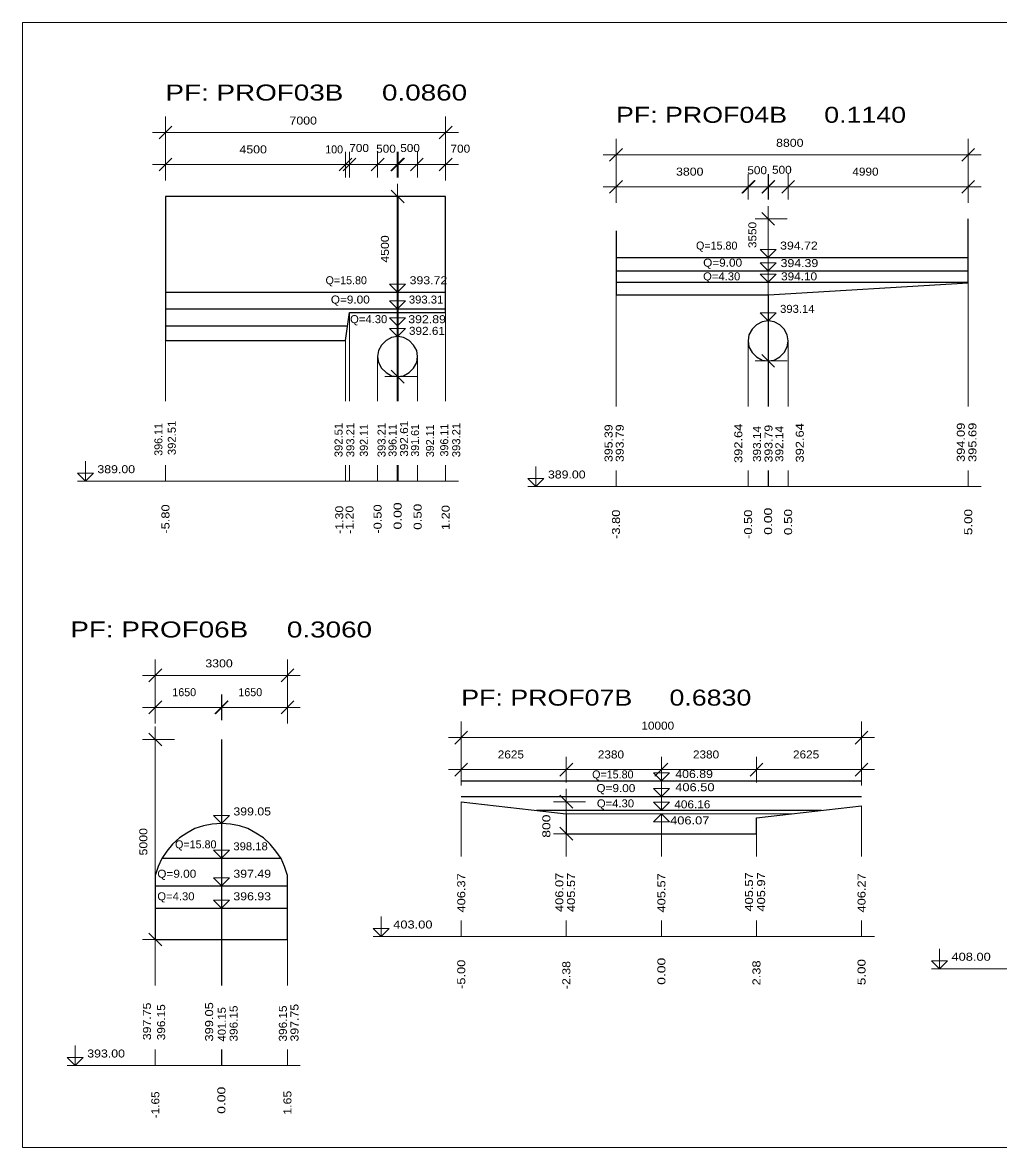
# Model space of a CAD drawing. Extents: x 7 to 442, y -393 to 441.
# Drawn here: x 17.84 to 42.23, y 76.44 to 104.55 of the extents above; entities that cross this region are included whole.
import ezdxf

# ---------------------------------------------------------------- set-up
doc = ezdxf.new("R2010")
doc.units = 0
doc.header["$LTSCALE"] = 0.08
doc.layers.add('63', color=7, linetype='Continuous', lineweight=13)
doc.layers.add('7', color=7, linetype='Continuous', lineweight=13)

msp = doc.modelspace()

# ---------------------------------------------------------------- linework, layer by layer
at = {"layer": '63'}
msp.add_lwpolyline([(17.844, 76.435), (17.844, 104.551), (38.081, 104.551), (58.318, 104.551), (58.318, 76.435), (38.081, 76.435)], close=True, dxfattribs=at)
at = {"layer": '7'}
for p, q in [((21.415, 100.6), (21.415, 102.2)), ((28.415, 100.6), (28.415, 102.2)), ((21.095, 101.8), (28.735, 101.8)), ((21.255, 101.64), (21.575, 101.96)), ((28.255, 101.64), (28.575, 101.96)), ((32.671, 100.044), (32.671, 101.644)), ((41.471, 100.044), (41.471, 101.644)), ((21.415, 100.68), (21.415, 101.32)), ((21.415, 100.68), (21.415, 101.32)), ((25.915, 100.68), (25.915, 101.32)), ((26.015, 100.68), (26.015, 101.32)), ((26.715, 100.68), (26.715, 101.32)), ((27.205, 100.68), (27.205, 101.32)), ((27.215, 100.68), (27.215, 101.32)), ((27.215, 100.68), (27.215, 101.32)), ((27.215, 100.68), (27.215, 101.32)), ((27.225, 100.68), (27.225, 101.32)), ((27.225, 100.68), (27.225, 101.32)), ((27.225, 100.68), (27.225, 101.32)), ((27.715, 100.68), (27.715, 101.32)), ((28.415, 100.68), (28.415, 101.32)), ((28.415, 100.68), (28.415, 101.32)), ((32.351, 101.244), (41.791, 101.244)), ((32.511, 101.084), (32.831, 101.404)), ((41.311, 101.084), (41.631, 101.404)), ((21.095, 101), (28.735, 101)), ((21.255, 100.84), (21.575, 101.16)), ((21.255, 100.84), (21.575, 101.16)), ((25.755, 100.84), (26.075, 101.16)), ((25.855, 100.84), (26.175, 101.16)), ((26.555, 100.84), (26.875, 101.16)), ((27.045, 100.84), (27.365, 101.16)), ((27.055, 100.84), (27.375, 101.16)), ((27.055, 100.84), (27.375, 101.16)), ((27.055, 100.84), (27.375, 101.16)), ((27.065, 100.84), (27.385, 101.16)), ((27.065, 100.84), (27.385, 101.16)), ((27.065, 100.84), (27.385, 101.16)), ((27.535, 100.84), (27.855, 101.16)), ((27.535, 100.84), (27.855, 101.16)), ((28.255, 100.84), (28.575, 101.16)), ((28.255, 100.84), (28.575, 101.16)), ((32.671, 100.124), (32.671, 100.764)), ((32.671, 100.124), (32.671, 100.764)), ((35.971, 100.124), (35.971, 100.764)), ((36.471, 100.124), (36.471, 100.764)), ((36.471, 100.124), (36.471, 100.764)), ((36.471, 100.124), (36.471, 100.764)), ((36.481, 100.124), (36.481, 100.764)), ((36.481, 100.124), (36.481, 100.764)), ((36.971, 100.124), (36.971, 100.764)), ((41.471, 100.124), (41.471, 100.764)), ((41.471, 100.124), (41.471, 100.764)), ((27.215, 95.54), (27.215, 100.52)), ((32.351, 100.444), (41.791, 100.444)), ((32.511, 100.284), (32.831, 100.604)), ((32.511, 100.284), (32.831, 100.604)), ((35.811, 100.284), (36.131, 100.604)), ((35.831, 100.284), (36.151, 100.604)), ((35.831, 100.284), (36.151, 100.604)), ((36.311, 100.284), (36.631, 100.604)), ((36.311, 100.284), (36.631, 100.604)), ((36.311, 100.284), (36.631, 100.604)), ((36.321, 100.284), (36.641, 100.604)), ((36.321, 100.284), (36.641, 100.604)), ((36.811, 100.284), (37.131, 100.604)), ((41.311, 100.284), (41.631, 100.604)), ((41.311, 100.284), (41.631, 100.604)), ((21.415, 95.087), (21.415, 100.2)), ((26.895, 100.2), (27.695, 100.2)), ((27.375, 100.04), (27.055, 100.36)), ((27.205, 95.087), (27.205, 100.2)), ((27.225, 95.087), (27.225, 100.2)), ((28.415, 95.087), (28.415, 100.2)), ((36.471, 95.934), (36.471, 99.964)), ((36.151, 99.644), (36.951, 99.644)), ((36.631, 99.484), (36.311, 99.804)), ((41.471, 94.955), (41.471, 99.644)), ((32.671, 94.955), (32.671, 99.344)), ((41.471, 94.955), (41.471, 98.044)), ((32.671, 94.955), (32.671, 97.744)), ((36.471, 94.955), (36.471, 97.744)), ((36.481, 94.955), (36.481, 97.744)), ((26.015, 95.087), (26.015, 97.3)), ((27.215, 95.087), (27.215, 97.3)), ((27.225, 95.087), (27.225, 97.3)), ((28.415, 95.087), (28.415, 97.3)), ((36.471, 94.955), (36.471, 97.094)), ((36.471, 97.094), (36.481, 97.094)), ((36.481, 94.955), (36.481, 97.094)), ((21.415, 95.087), (21.415, 96.6)), ((25.915, 95.087), (25.915, 96.6)), ((27.215, 95.087), (27.215, 96.7)), ((27.225, 95.087), (27.225, 96.7)), ((35.971, 94.955), (35.971, 96.594)), ((36.971, 94.955), (36.971, 96.594)), ((26.715, 95.087), (26.715, 96.2)), ((27.715, 95.087), (27.715, 96.2)), ((36.631, 95.934), (36.311, 96.254)), ((36.151, 96.094), (36.951, 96.094)), ((36.471, 94.955), (36.471, 96.094)), ((26.895, 95.7), (27.695, 95.7)), ((27.375, 95.54), (27.055, 95.86)), ((27.215, 95.087), (27.215, 95.7)), ((21.415, 93.087), (21.415, 93.487)), ((21.415, 93.087), (21.415, 93.487)), ((25.915, 93.087), (25.915, 93.487)), ((26.015, 93.087), (26.015, 93.487)), ((26.715, 93.087), (26.715, 93.487)), ((27.205, 93.087), (27.205, 93.487)), ((27.215, 93.087), (27.215, 93.487)), ((27.215, 93.087), (27.215, 93.487)), ((27.215, 93.087), (27.215, 93.487)), ((27.225, 93.087), (27.225, 93.487)), ((27.225, 93.087), (27.225, 93.487)), ((27.225, 93.087), (27.225, 93.487)), ((27.715, 93.087), (27.715, 93.487)), ((28.415, 93.087), (28.415, 93.487)), ((28.415, 93.087), (28.415, 93.487)), ((32.671, 92.955), (32.671, 93.355)), ((32.671, 92.955), (32.671, 93.355)), ((35.971, 92.955), (35.971, 93.355)), ((36.471, 92.955), (36.471, 93.355)), ((36.471, 92.955), (36.471, 93.355)), ((36.471, 92.955), (36.471, 93.355)), ((36.481, 92.955), (36.481, 93.355)), ((36.481, 92.955), (36.481, 93.355)), ((36.971, 92.955), (36.971, 93.355)), ((41.471, 92.955), (41.471, 93.355)), ((41.471, 92.955), (41.471, 93.355)), ((19.215, 93.087), (28.735, 93.087)), ((30.471, 92.955), (41.791, 92.955)), ((21.162, 87.034), (21.162, 88.634)), ((24.462, 87.034), (24.462, 88.634)), ((21.002, 88.074), (21.322, 88.394)), ((24.302, 88.074), (24.622, 88.394)), ((20.842, 88.234), (24.782, 88.234)), ((21.162, 87.114), (21.162, 87.754)), ((21.162, 87.114), (21.162, 87.754)), ((22.812, 87.114), (22.812, 87.754)), ((22.812, 87.114), (22.812, 87.754)), ((22.812, 87.114), (22.812, 87.754)), ((22.822, 87.114), (22.822, 87.754)), ((22.822, 87.114), (22.822, 87.754)), ((24.462, 87.114), (24.462, 87.754)), ((24.462, 87.114), (24.462, 87.754)), ((21.002, 87.274), (21.322, 87.594)), ((21.002, 87.274), (21.322, 87.594)), ((22.652, 87.274), (22.972, 87.594)), ((22.652, 87.274), (22.972, 87.594)), ((22.652, 87.274), (22.972, 87.594)), ((22.662, 87.274), (22.982, 87.594)), ((22.662, 87.274), (22.982, 87.594)), ((24.302, 87.274), (24.622, 87.594)), ((24.302, 87.274), (24.622, 87.594)), ((20.842, 87.434), (24.782, 87.434)), ((21.162, 81.474), (21.162, 86.954)), ((28.805, 85.478), (28.805, 87.078)), ((38.805, 85.478), (38.805, 87.078)), ((20.842, 86.634), (21.642, 86.634)), ((21.322, 86.474), (21.002, 86.794)), ((22.812, 80.484), (22.812, 86.634)), ((22.822, 80.484), (22.822, 86.634)), ((28.485, 86.678), (39.125, 86.678)), ((28.645, 86.518), (28.965, 86.838)), ((38.645, 86.518), (38.965, 86.838)), ((28.645, 85.718), (28.965, 86.038)), ((28.805, 85.558), (28.805, 86.198)), ((31.27, 85.718), (31.59, 86.038)), ((31.27, 85.718), (31.59, 86.038)), ((31.43, 85.558), (31.43, 86.198)), ((31.43, 85.558), (31.43, 86.198)), ((33.645, 85.718), (33.965, 86.038)), ((33.805, 85.558), (33.805, 86.198)), ((36.02, 85.718), (36.34, 86.038)), ((36.02, 85.718), (36.34, 86.038)), ((36.18, 85.558), (36.18, 86.198)), ((36.18, 85.558), (36.18, 86.198)), ((38.645, 85.718), (38.965, 86.038)), ((38.805, 85.558), (38.805, 86.198)), ((28.485, 85.878), (39.125, 85.878)), ((31.59, 84.918), (31.27, 85.238)), ((31.43, 84.118), (31.43, 85.398)), ((28.805, 83.708), (28.805, 85.078)), ((31.11, 85.078), (31.91, 85.078)), ((38.805, 83.708), (38.805, 84.978)), ((31.43, 83.708), (31.43, 84.778)), ((31.43, 84.778), (37.055, 84.778)), ((36.18, 83.708), (36.18, 84.678)), ((22.812, 80.484), (22.812, 84.534)), ((22.812, 84.534), (22.822, 84.534)), ((22.822, 80.484), (22.822, 84.534)), ((31.59, 84.118), (31.27, 84.438)), ((31.11, 84.278), (31.91, 84.278)), ((31.43, 83.708), (31.43, 84.278)), ((33.805, 83.708), (33.805, 84.278)), ((36.18, 83.708), (36.18, 84.278)), ((21.162, 80.484), (21.162, 83.234)), ((24.462, 80.484), (24.462, 83.234)), ((28.805, 81.708), (28.805, 82.108)), ((31.43, 81.708), (31.43, 82.108)), ((31.43, 81.708), (31.43, 82.108)), ((33.805, 81.708), (33.805, 82.108)), ((36.18, 81.708), (36.18, 82.108)), ((36.18, 81.708), (36.18, 82.108)), ((38.805, 81.708), (38.805, 82.108)), ((20.842, 81.634), (21.642, 81.634)), ((21.322, 81.474), (21.002, 81.794)), ((21.162, 80.484), (21.162, 81.634)), ((22.812, 80.484), (22.812, 81.634)), ((24.462, 80.484), (24.462, 81.634)), ((26.605, 81.708), (39.125, 81.708)), ((40.552, 80.902), (61.772, 80.902)), ((21.162, 78.484), (21.162, 78.884)), ((21.162, 78.484), (21.162, 78.884)), ((22.812, 78.484), (22.812, 78.884)), ((22.812, 78.484), (22.812, 78.884)), ((22.812, 78.484), (22.812, 78.884)), ((22.822, 78.484), (22.822, 78.884)), ((22.822, 78.484), (22.822, 78.884)), ((24.462, 78.484), (24.462, 78.884)), ((24.462, 78.484), (24.462, 78.884)), ((18.962, 78.484), (24.782, 78.484))]:
    msp.add_line(p, q, dxfattribs=at)
at = {"layer": '7', "lineweight": 25}
for p, q in [((32.671, 98.676), (41.471, 98.676)), ((32.671, 98.343), (41.471, 98.343)), ((32.671, 98.058), (41.471, 98.058)), ((21.415, 97.809), (28.415, 97.809)), ((21.415, 97.396), (28.415, 97.396)), ((21.415, 96.974), (25.968, 96.974)), ((28.805, 85.599), (38.805, 85.599)), ((28.805, 85.21), (38.805, 85.21)), ((30.683, 84.863), (37.802, 84.863)), ((21.327, 83.662), (24.297, 83.662)), ((21.162, 82.977), (24.462, 82.977)), ((21.162, 82.413), (24.462, 82.413))]:
    msp.add_line(p, q, dxfattribs=at)
for points in [[(27.205, 100.2), (21.415, 100.2), (21.415, 96.6), (25.915, 96.6), (26.015, 97.3), (27.215, 97.3), (27.215, 96.7), (27.065, 96.68), (26.925, 96.6), (26.815, 96.49), (26.735, 96.35), (26.715, 96.2), (26.735, 96.05), (26.815, 95.91), (26.925, 95.8), (27.065, 95.72), (27.215, 95.7), (27.365, 95.72), (27.505, 95.8), (27.615, 95.91), (27.695, 96.05), (27.715, 96.2), (27.695, 96.35), (27.615, 96.49), (27.505, 96.6), (27.365, 96.68), (27.225, 96.7), (27.225, 97.3), (28.415, 97.3), (28.415, 100.2), (27.225, 100.2)], [(32.671, 99.344), (32.671, 97.744), (36.471, 97.744), (36.471, 97.094), (36.321, 97.074), (36.181, 96.994), (36.071, 96.884), (35.991, 96.744), (35.971, 96.594), (35.991, 96.444), (36.071, 96.304), (36.181, 96.194), (36.321, 96.114), (36.471, 96.094), (36.621, 96.114), (36.761, 96.194), (36.871, 96.304), (36.951, 96.444), (36.971, 96.594), (36.951, 96.744), (36.871, 96.884), (36.761, 96.994), (36.621, 97.074), (36.481, 97.094), (36.481, 97.744), (41.471, 98.044), (41.471, 99.644)], [(22.812, 86.634), (22.812, 84.534), (22.582, 84.514), (22.362, 84.474), (22.152, 84.404), (21.952, 84.294), (21.762, 84.174), (21.592, 84.014), (21.452, 83.844), (21.322, 83.654), (21.232, 83.454), (21.162, 83.234), (21.162, 81.634), (22.812, 81.634), (24.462, 81.634), (24.462, 83.234), (24.392, 83.454), (24.302, 83.654), (24.172, 83.844), (24.032, 84.014), (23.862, 84.174), (23.672, 84.294), (23.472, 84.404), (23.262, 84.474), (23.042, 84.514), (22.822, 84.534), (22.822, 86.634)], [(28.805, 85.078), (31.43, 84.778), (31.43, 84.278), (33.805, 84.278), (36.18, 84.278), (36.18, 84.678), (38.805, 84.978)]]:
    msp.add_lwpolyline(points, dxfattribs=at)
at = {"layer": '7'}
for points in [[(36.471, 99.176), (36.471, 98.676), (36.271, 98.876), (36.671, 98.876), (36.471, 98.676)], [(36.471, 98.843), (36.471, 98.343), (36.271, 98.543), (36.671, 98.543), (36.471, 98.343)], [(36.471, 98.558), (36.471, 98.058), (36.271, 98.258), (36.671, 98.258), (36.471, 98.058)], [(27.215, 98.309), (27.215, 97.809), (27.015, 98.009), (27.415, 98.009), (27.215, 97.809)], [(27.215, 97.896), (27.215, 97.396), (27.015, 97.596), (27.415, 97.596), (27.215, 97.396)], [(36.471, 97.594), (36.471, 97.094), (36.271, 97.294), (36.671, 97.294), (36.471, 97.094)], [(27.215, 97.474), (27.215, 96.974), (27.015, 97.174), (27.415, 97.174), (27.215, 96.974), (27.225, 96.974)], [(27.215, 97.2), (27.215, 96.7), (27.015, 96.9), (27.415, 96.9), (27.215, 96.7), (27.225, 96.7)], [(19.415, 93.587), (19.415, 93.087), (19.215, 93.287), (19.615, 93.287), (19.415, 93.087)], [(30.671, 93.455), (30.671, 92.955), (30.471, 93.155), (30.871, 93.155), (30.671, 92.955)], [(33.805, 86.099), (33.805, 85.599), (33.605, 85.799), (34.005, 85.799), (33.805, 85.599)], [(33.805, 85.71), (33.805, 85.21), (33.605, 85.41), (34.005, 85.41), (33.805, 85.21)], [(33.805, 85.363), (33.805, 84.863), (33.605, 85.063), (34.005, 85.063), (33.805, 84.863)], [(22.812, 85.034), (22.812, 84.534), (22.612, 84.734), (23.012, 84.734), (22.812, 84.534)], [(33.805, 84.278), (33.805, 84.778), (34.005, 84.578), (33.605, 84.578), (33.805, 84.778)], [(22.812, 84.162), (22.812, 83.662), (22.612, 83.862), (23.012, 83.862), (22.812, 83.662)], [(22.812, 83.477), (22.812, 82.977), (22.612, 83.177), (23.012, 83.177), (22.812, 82.977)], [(22.812, 82.913), (22.812, 82.413), (22.612, 82.613), (23.012, 82.613), (22.812, 82.413)], [(26.805, 82.208), (26.805, 81.708), (26.605, 81.908), (27.005, 81.908), (26.805, 81.708)], [(40.752, 81.402), (40.752, 80.902), (40.552, 81.102), (40.952, 81.102), (40.752, 80.902)], [(19.162, 78.984), (19.162, 78.484), (18.962, 78.684), (19.362, 78.684), (19.162, 78.484)]]:
    msp.add_lwpolyline(points, dxfattribs=at)

# ---------------------------------------------------------------- texts
for s, height, width, p in [('PF: PROF03B     0.0860', 0.4, 1.3, (21.415, 102.6)), ('PF: PROF04B     0.1140', 0.4, 1.25, (32.671, 102.044)), ('7000', 0.2, 1.15, (24.515, 102)), ('700', 0.2, 1.1, (26.008, 101.315)), ('500', 0.2, 1.1, (26.679, 101.297)), ('500', 0.2, 1.1, (27.281, 101.315)), ('700', 0.2, 1.1, (28.537, 101.298)), ('8800', 0.2, 1.15, (36.671, 101.444)), ('4500', 0.2, 1.15, (23.265, 101.28)), ('500', 0.2, 1.1, (35.952, 100.759)), ('500', 0.2, 1.1, (36.569, 100.77)), ('3800', 0.2, 1.15, (34.171, 100.724)), ('4990', 0.2, 1.1, (38.576, 100.724)), ('394.72', 0.2, 1.15, (36.771, 98.876)), ('Q=9.00', 0.2, 1.1, (34.848, 98.449)), ('394.39', 0.2, 1.15, (36.783, 98.438)), ('393.72', 0.2, 1.15, (27.515, 98.009)), ('Q=4.30', 0.2, 1.05, (34.847, 98.107)), ('394.10', 0.2, 1.1, (36.795, 98.107)), ('Q=9.00', 0.2, 1.1, (25.546, 97.527)), ('393.31', 0.2, 1.05, (27.497, 97.527)), ('393.14', 0.2, 1.05, (36.771, 97.294)), ('Q=4.30', 0.2, 1.05, (26.028, 97.037)), ('392.89', 0.2, 1.15, (27.481, 97.036)), ('392.61', 0.2, 1.1, (27.498, 96.745)), ('389.00', 0.2, 1.15, (19.715, 93.287)), ('389.00', 0.2, 1.15, (30.971, 93.155)), ('PF: PROF06B     0.3060', 0.4, 1.3, (19.039, 89.181)), ('3300', 0.2, 1.15, (22.412, 88.434)), ('PF: PROF07B     0.6830', 0.4, 1.25, (28.805, 87.478)), ('10000', 0.2, 1.1, (33.305, 86.878)), ('2625', 0.2, 1.1, (29.717, 86.158)), ('2380', 0.2, 1.1, (32.217, 86.158)), ('2380', 0.2, 1.1, (34.593, 86.158)), ('2625', 0.2, 1.1, (37.093, 86.158)), ('406.89', 0.2, 1.15, (34.152, 85.67)), ('Q=9.00', 0.2, 1.1, (32.181, 85.317)), ('406.50', 0.2, 1.2, (34.151, 85.339)), ('399.05', 0.2, 1.15, (23.112, 84.734)), ('Q=4.30', 0.2, 1.05, (32.193, 84.935)), ('406.16', 0.2, 1.1, (34.128, 84.911)), ('406.07', 0.2, 1.2, (34.023, 84.51)), ('398.18', 0.2, 1.05, (23.112, 83.862)), ('Q=9.00', 0.2, 1.1, (21.212, 83.177)), ('397.49', 0.2, 1.15, (23.112, 83.177)), ('Q=4.30', 0.2, 1.05, (21.212, 82.613)), ('396.93', 0.2, 1.15, (23.112, 82.613)), ('403.00', 0.2, 1.2, (27.105, 81.908)), ('408.00', 0.2, 1.2, (41.052, 81.102)), ('393.00', 0.2, 1.15, (19.462, 78.684))]:
    msp.add_text(s, height=height, dxfattribs=dict(at, width=width)).set_placement(p)
for s, p in [('100', (25.406, 101.28)), ('Q=15.80', (34.671, 98.876)), ('Q=15.80', (25.415, 98.009)), ('1650', (21.587, 87.714)), ('1650', (23.237, 87.714)), ('Q=15.80', (32.075, 85.659)), ('Q=15.80', (21.656, 83.911))]:
    msp.add_text(s, height=0.2, dxfattribs=at).set_placement(p)
for s, width, p in [('3550', 1.1, (36.178, 98.913)), ('4500', 1.15, (26.997, 98.548)), ('392.51 ', 1.05, (21.673, 93.74)), ('392.51 ', 1.05, (25.839, 93.687)), ('393.21 ', 1.05, (26.133, 93.687)), ('393.21 ', 1.05, (26.914, 93.687)), ('392.61 ', 1.1, (27.476, 93.698)), ('393.21 ', 1.05, (28.779, 93.687)), ('395.39 ', 1.15, (32.585, 93.567)), ('393.79 ', 1.15, (32.864, 93.566)), ('392.64 ', 1.2, (35.827, 93.543)), ('393.79 ', 1.15, (36.581, 93.555)), ('392.64 ', 1.2, (37.362, 93.555)), ('394.09 ', 1.2, (41.385, 93.567)), ('395.69 ', 1.2, (41.675, 93.567)), ('393.14 ', 1.1, (36.292, 93.567)), ('392.14 ', 1.1, (36.851, 93.567)), ('  0.00 ', 1.3, (27.315, 91.687)), ('  0.00 ', 1.3, (27.315, 91.687)), ('  0.50 ', 1.25, (27.815, 91.687)), (' -5.80 ', 1.2, (21.515, 91.687)), (' -5.80 ', 1.2, (21.515, 91.687)), (' -1.30 ', 1.15, (25.857, 91.687)), (' -1.20 ', 1.15, (26.115, 91.687)), (' -0.50 ', 1.2, (26.815, 91.687)), ('  1.20 ', 1.2, (28.515, 91.687)), ('  1.20 ', 1.2, (28.515, 91.687)), (' -3.80 ', 1.2, (32.771, 91.555)), (' -3.80 ', 1.2, (32.771, 91.555)), (' -0.50 ', 1.2, (36.071, 91.555)), ('  0.00 ', 1.3, (36.571, 91.555)), ('  0.00 ', 1.3, (36.571, 91.555)), ('  0.00 ', 1.3, (36.571, 91.555)), ('  0.50 ', 1.25, (37.071, 91.555)), ('  5.00 ', 1.25, (41.571, 91.555)), ('  5.00 ', 1.25, (41.571, 91.555)), (' 800', 1.3, (31.031, 84.079)), ('5000', 1.15, (20.962, 83.734)), ('406.37 ', 1.2, (28.905, 82.308)), ('406.07 ', 1.2, (31.355, 82.32)), ('405.57 ', 1.2, (31.647, 82.319)), ('405.57 ', 1.2, (33.905, 82.308)), ('405.57 ', 1.2, (36.093, 82.331)), ('405.97 ', 1.2, (36.397, 82.332)), ('406.27 ', 1.2, (38.905, 82.308)), (' -5.00 ', 1.2, (28.905, 80.308)), (' -2.38 ', 1.15, (31.53, 80.308)), (' -2.38 ', 1.15, (31.53, 80.308)), ('  0.00 ', 1.3, (33.905, 80.308)), ('  2.38 ', 1.2, (36.28, 80.308)), ('  2.38 ', 1.2, (36.28, 80.308)), ('  5.00 ', 1.25, (38.905, 80.308)), ('397.75 ', 1.15, (21.053, 79.116)), ('396.15 ', 1.1, (21.407, 79.116)), ('399.05 ', 1.2, (22.606, 79.084)), ('401.15 ', 1.05, (22.922, 79.084)), ('396.15 ', 1.1, (23.218, 79.084)), ('396.15 ', 1.1, (24.448, 79.084)), ('397.75 ', 1.15, (24.739, 79.084)), ('  0.00 ', 1.3, (22.912, 77.084)), ('  0.00 ', 1.3, (22.912, 77.084)), ('  0.00 ', 1.3, (22.912, 77.084)), (' -1.65 ', 1.1, (21.262, 77.084)), (' -1.65 ', 1.1, (21.262, 77.084)), ('  1.65 ', 1.15, (24.562, 77.084)), ('  1.65 ', 1.15, (24.562, 77.084))]:
    msp.add_text(s, height=0.2, rotation=90, dxfattribs=dict(at, width=width)).set_placement(p)
for s, p in [('396.11 ', (21.339, 93.722)), ('392.11 ', (26.471, 93.698)), ('396.11 ', (27.188, 93.699)), ('391.61 ', (27.75, 93.699)), ('392.11 ', (28.125, 93.687)), ('396.11 ', (28.48, 93.705))]:
    msp.add_text(s, height=0.2, rotation=90, dxfattribs=at).set_placement(p)

doc.saveas('drawing.dxf')
